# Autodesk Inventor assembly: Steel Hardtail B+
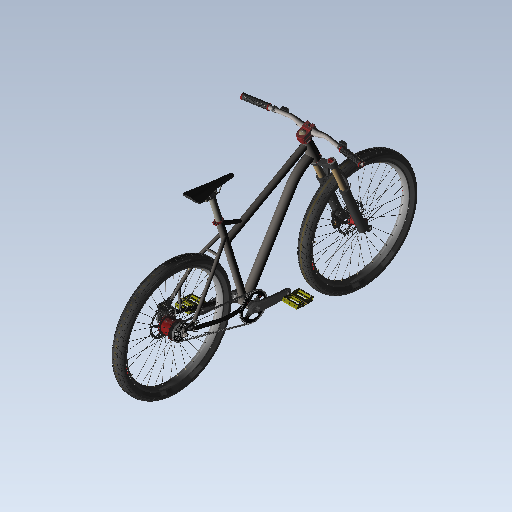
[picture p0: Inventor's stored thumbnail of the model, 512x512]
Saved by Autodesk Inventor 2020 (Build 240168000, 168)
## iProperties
Created: 2017-09
Part Number: Steel Hardtail B+
Material: Ogólny
Document SubType Name: Assembly
Designer: Tomasz
Sending System: SolidWorks 2017
Last Author: Tomasz
Last Saved: 2017-11-20
Author: Tomasz
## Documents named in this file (43)
- C:\Users\bruno\Documents\1-Cours-2020-21\1STI2D-2020-21\IT\6. Antivol\Inventor-Antivol\INVENTOR 2018_Steel Hardtail B+\Vélo.iam
- C:\Users\bruno\Documents\1-Cours-2020-21\1STI2D-2020-21\IT\6. Antivol\Inventor-Antivol\INVENTOR 2018_Steel Hardtail B+\Stalowa rama e-MTB - silnik w piaście.ipt
- C:\Users\bruno\Documents\1-Cours-2020-21\1STI2D-2020-21\IT\6. Antivol\Inventor-Antivol\INVENTOR 2018_Steel Hardtail B+\DR4005.ipt
- C:\Users\bruno\Documents\1-Cours-2020-21\1STI2D-2020-21\IT\6. Antivol\Inventor-Antivol\INVENTOR 2018_Steel Hardtail B+\MS1013.ipt
- C:\Users\bruno\Documents\1-Cours-2020-21\1STI2D-2020-21\IT\6. Antivol\Inventor-Antivol\INVENTOR 2018_Steel Hardtail B+\MS2012.ipt
- C:\Users\bruno\Documents\1-Cours-2020-21\1STI2D-2020-21\IT\6. Antivol\Inventor-Antivol\INVENTOR 2018_Steel Hardtail B+\MS2013.ipt
- C:\Users\bruno\Documents\1-Cours-2020-21\1STI2D-2020-21\IT\6. Antivol\Inventor-Antivol\INVENTOR 2018_Steel Hardtail B+\MS2016.ipt
- C:\Users\bruno\Documents\1-Cours-2020-21\1STI2D-2020-21\IT\6. Antivol\Inventor-Antivol\INVENTOR 2018_Steel Hardtail B+\MS2017.ipt
- C:\Users\bruno\Documents\1-Cours-2020-21\1STI2D-2020-21\IT\6. Antivol\Inventor-Antivol\INVENTOR 2018_Steel Hardtail B+\MS5001.ipt
- C:\Users\bruno\Documents\1-Cours-2020-21\1STI2D-2020-21\IT\6. Antivol\Inventor-Antivol\INVENTOR 2018_Steel Hardtail B+\DR4025.ipt
- C:\Users\bruno\Documents\1-Cours-2020-21\1STI2D-2020-21\IT\6. Antivol\Inventor-Antivol\INVENTOR 2018_Steel Hardtail B+\MS1013_2.ipt
- C:\Users\bruno\Documents\1-Cours-2020-21\1STI2D-2020-21\IT\6. Antivol\Inventor-Antivol\INVENTOR 2018_Steel Hardtail B+\MS2012_1.ipt
- C:\Users\bruno\Documents\1-Cours-2020-21\1STI2D-2020-21\IT\6. Antivol\Inventor-Antivol\INVENTOR 2018_Steel Hardtail B+\MS2012_2.ipt
- C:\Users\bruno\Documents\1-Cours-2020-21\1STI2D-2020-21\IT\6. Antivol\Inventor-Antivol\INVENTOR 2018_Steel Hardtail B+\MS2013_2.ipt
- C:\Users\bruno\Documents\1-Cours-2020-21\1STI2D-2020-21\IT\6. Antivol\Inventor-Antivol\INVENTOR 2018_Steel Hardtail B+\MS2016_2.ipt
- C:\Users\bruno\Documents\1-Cours-2020-21\1STI2D-2020-21\IT\6. Antivol\Inventor-Antivol\INVENTOR 2018_Steel Hardtail B+\MS5001_2.ipt
- C:\Users\bruno\Documents\1-Cours-2020-21\1STI2D-2020-21\IT\6. Antivol\Inventor-Antivol\INVENTOR 2018_Steel Hardtail B+\lower set.iam
- C:\Users\bruno\Documents\1-Cours-2020-21\1STI2D-2020-21\IT\6. Antivol\Inventor-Antivol\INVENTOR 2018_Steel Hardtail B+\Upper set.iam
- C:\Users\bruno\Documents\1-Cours-2020-21\1STI2D-2020-21\IT\6. Antivol\Inventor-Antivol\INVENTOR 2018_Steel Hardtail B+\FOX 32.ipt
- C:\Users\bruno\Documents\1-Cours-2020-21\1STI2D-2020-21\IT\6. Antivol\Inventor-Antivol\INVENTOR 2018_Steel Hardtail B+\front wheel assembly Solidworks.iam
- C:\Users\bruno\Documents\1-Cours-2020-21\1STI2D-2020-21\IT\6. Antivol\Inventor-Antivol\INVENTOR 2018_Steel Hardtail B+\Rear wheel assembly.iam.iam
- C:\Users\bruno\Documents\1-Cours-2020-21\1STI2D-2020-21\IT\6. Antivol\Inventor-Antivol\INVENTOR 2018_Steel Hardtail B+\NS quark stem.iam
- C:\Users\bruno\Documents\1-Cours-2020-21\1STI2D-2020-21\IT\6. Antivol\Inventor-Antivol\INVENTOR 2018_Steel Hardtail B+\Headtube spacer.ipt
- C:\Users\bruno\Documents\1-Cours-2020-21\1STI2D-2020-21\IT\6. Antivol\Inventor-Antivol\INVENTOR 2018_Steel Hardtail B+\top cap.ipt
- C:\Users\bruno\Documents\1-Cours-2020-21\1STI2D-2020-21\IT\6. Antivol\Inventor-Antivol\INVENTOR 2018_Steel Hardtail B+\socket head cap screw_iso.ipt
- C:\Users\bruno\Documents\1-Cours-2020-21\1STI2D-2020-21\IT\6. Antivol\Inventor-Antivol\INVENTOR 2018_Steel Hardtail B+\MTB Handlebar.ipt
- C:\Users\bruno\Documents\1-Cours-2020-21\1STI2D-2020-21\IT\6. Antivol\Inventor-Antivol\INVENTOR 2018_Steel Hardtail B+\Dartmoor Race 145mm.iam
- C:\Users\bruno\Documents\1-Cours-2020-21\1STI2D-2020-21\IT\6. Antivol\Inventor-Antivol\INVENTOR 2018_Steel Hardtail B+\Seat clamp 31,6.iam.iam
- C:\Users\bruno\Documents\1-Cours-2020-21\1STI2D-2020-21\IT\6. Antivol\Inventor-Antivol\INVENTOR 2018_Steel Hardtail B+\socket head cap screw_iso_ISO 4762 M5 x 16 - 16N.ipt
- C:\Users\bruno\Documents\1-Cours-2020-21\1STI2D-2020-21\IT\6. Antivol\Inventor-Antivol\INVENTOR 2018_Steel Hardtail B+\torque nut 12_iso.ipt
- C:\Users\bruno\Documents\1-Cours-2020-21\1STI2D-2020-21\IT\6. Antivol\Inventor-Antivol\INVENTOR 2018_Steel Hardtail B+\Kopia Bottom Bracket BSA-Comp.iam^Rear hub motor ebike.iam
- C:\Users\bruno\Documents\1-Cours-2020-21\1STI2D-2020-21\IT\6. Antivol\Inventor-Antivol\INVENTOR 2018_Steel Hardtail B+\Gates Carbon Drive belt 448.47mm.iam
- C:\Users\bruno\Documents\1-Cours-2020-21\1STI2D-2020-21\IT\6. Antivol\Inventor-Antivol\INVENTOR 2018_Steel Hardtail B+\Shimano Deore XT Crankset.iam
- C:\Users\bruno\Documents\1-Cours-2020-21\1STI2D-2020-21\IT\6. Antivol\Inventor-Antivol\INVENTOR 2018_Steel Hardtail B+\Pedal washer.ipt
- C:\Users\bruno\Documents\1-Cours-2020-21\1STI2D-2020-21\IT\6. Antivol\Inventor-Antivol\INVENTOR 2018_Steel Hardtail B+\Left pedal.iam
- C:\Users\bruno\Documents\1-Cours-2020-21\1STI2D-2020-21\IT\6. Antivol\Inventor-Antivol\INVENTOR 2018_Steel Hardtail B+\Right pedal.iam
- C:\Users\bruno\Documents\1-Cours-2020-21\1STI2D-2020-21\IT\6. Antivol\Inventor-Antivol\INVENTOR 2018_Steel Hardtail B+\HOPE MONO M4_right.iam
- C:\Users\bruno\Documents\1-Cours-2020-21\1STI2D-2020-21\IT\6. Antivol\Inventor-Antivol\INVENTOR 2018_Steel Hardtail B+\HOPE MONO M4_Left.iam
- C:\Users\bruno\Documents\1-Cours-2020-21\1STI2D-2020-21\IT\6. Antivol\Inventor-Antivol\INVENTOR 2018_Steel Hardtail B+\Hope_Mono M4_Caliper.ipt
- C:\Users\bruno\Documents\1-Cours-2020-21\1STI2D-2020-21\IT\6. Antivol\Inventor-Antivol\INVENTOR 2018_Steel Hardtail B+\Kopia Fork Axle.ipt^Rear hub motor ebike.ipt
- C:\Users\bruno\Documents\1-Cours-2020-21\1STI2D-2020-21\IT\6. Antivol\Inventor-Antivol\INVENTOR 2018_Steel Hardtail B+\Seatpost and saddle 31_6.iam
- Rear wheel assembly.iam
- Seat clamp 31,6.iam
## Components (45 placed, 39 different names)
1. Stalowa rama e-MTB - silnik w piaście:3 — Zestawiający:1
2. DR4005:1
3. MS1013:1
4. MS2012:1
5. MS2013:1
6. MS2016:1
7. MS2017:1
8. MS5001:1
9. MS2012:2
10. DR4025:1
11. MS1013_2:1
12. MS2012_1:1
13. MS2012_2:1
14. MS2013_2:1
15. MS2016_2:1
16. MS5001_2:1
17. lower set:1 [sub-assembly]
18. Upper set:1 [sub-assembly]
19. FOX 32:1
20. front wheel assembly Solidworks:1 [sub-assembly]
21. Rear wheel assembly.iam:1 [sub-assembly]
22. NS quark stem:1 [sub-assembly]
23. Headtube spacer:1
24. top cap:1
25. socket head cap screw_iso:2
26. MTB Handlebar:1
27. Dartmoor Race 145mm:1 [sub-assembly]
28. Dartmoor Race 145mm:2 [sub-assembly]
29. Seat clamp 31,6.iam:1 [sub-assembly] — Zestawiający:2, Kąt:1
30. socket head cap screw_iso:3
31. torque nut 12_iso:1
32. torque nut 12_iso:2
33. Kopia Bottom Bracket BSA-Comp.iam^Rear hub motor ebike:1 [sub-assembly]
34. Gates Carbon Drive belt 448.47mm:1 [sub-assembly]
35. Shimano Deore XT Crankset:1 [sub-assembly]
36. Pedal washer:1
37. Pedal washer:2
38. Left pedal:1 [sub-assembly]
39. Right pedal:1 [sub-assembly]
40. HOPE MONO M4_right:1 [sub-assembly]
41. HOPE MONO M4_Left:1 [sub-assembly]
42. Hope_Mono M4_Caliper:1
43. Hope_Mono M4_Caliper:2
44. Kopia Fork Axle.ipt^Rear hub motor ebike:1
45. Seatpost and saddle 31_6:1 [sub-assembly] — Zestawiający:1, Zestawiający:2, Kąt:1
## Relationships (3: Mate 2, Angle 1)
- Zestawiający:1 [Mate]: Stalowa rama e-MTB - silnik w piaście:3 ↔ Seatpost and saddle 31_6:1
- Zestawiający:2 [Mate]: Seat clamp 31,6.iam:1 ↔ Seatpost and saddle 31_6:1
- Kąt:1 [Angle]: Seat clamp 31,6.iam:1 ↔ Seatpost and saddle 31_6:1
